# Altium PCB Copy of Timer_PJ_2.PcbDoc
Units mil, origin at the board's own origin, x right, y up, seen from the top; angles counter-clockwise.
Board outline 6000 x 4000 mil, 2 copper layers (Top Layer, Bottom Layer); 19 components, 12 nets, 42 pads, 0 vias.
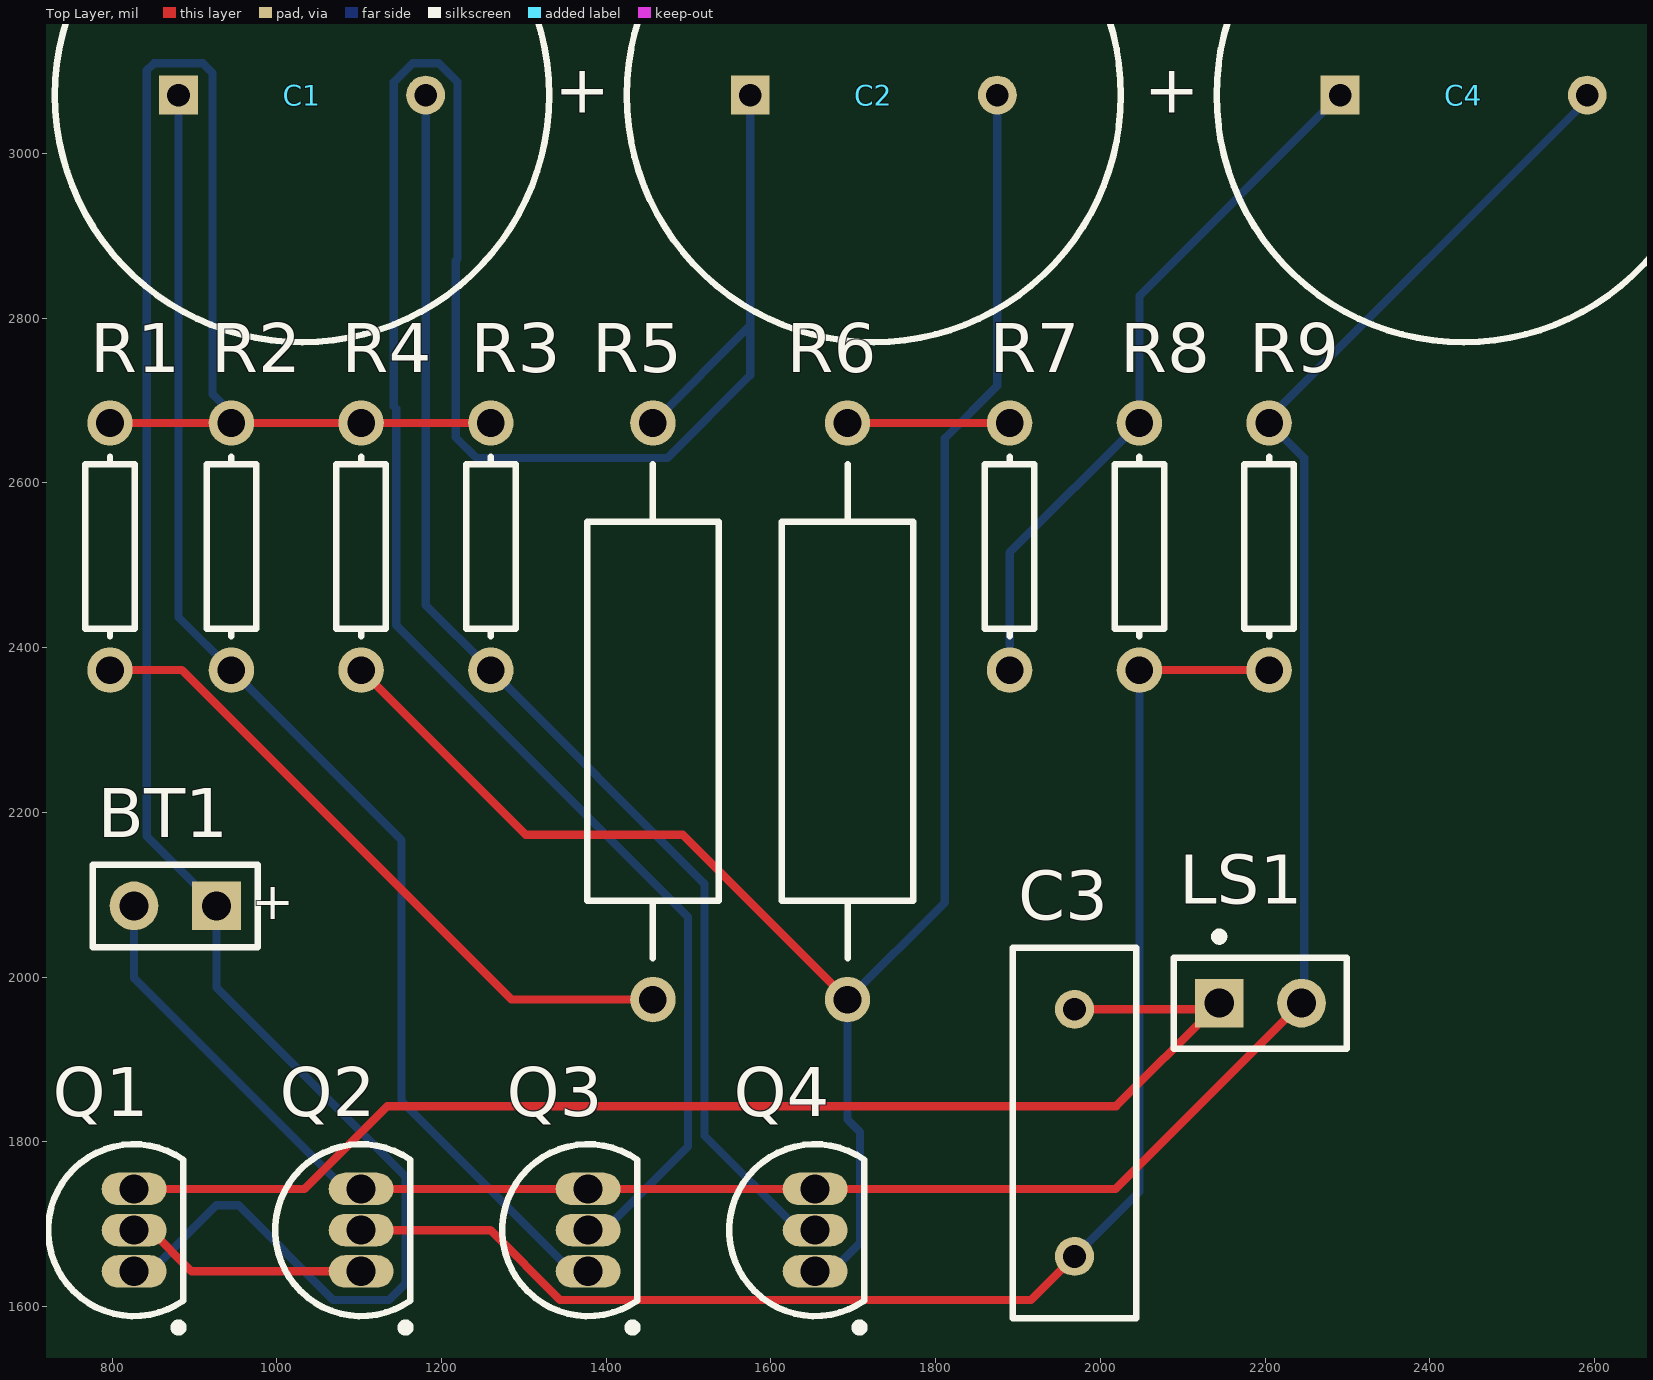
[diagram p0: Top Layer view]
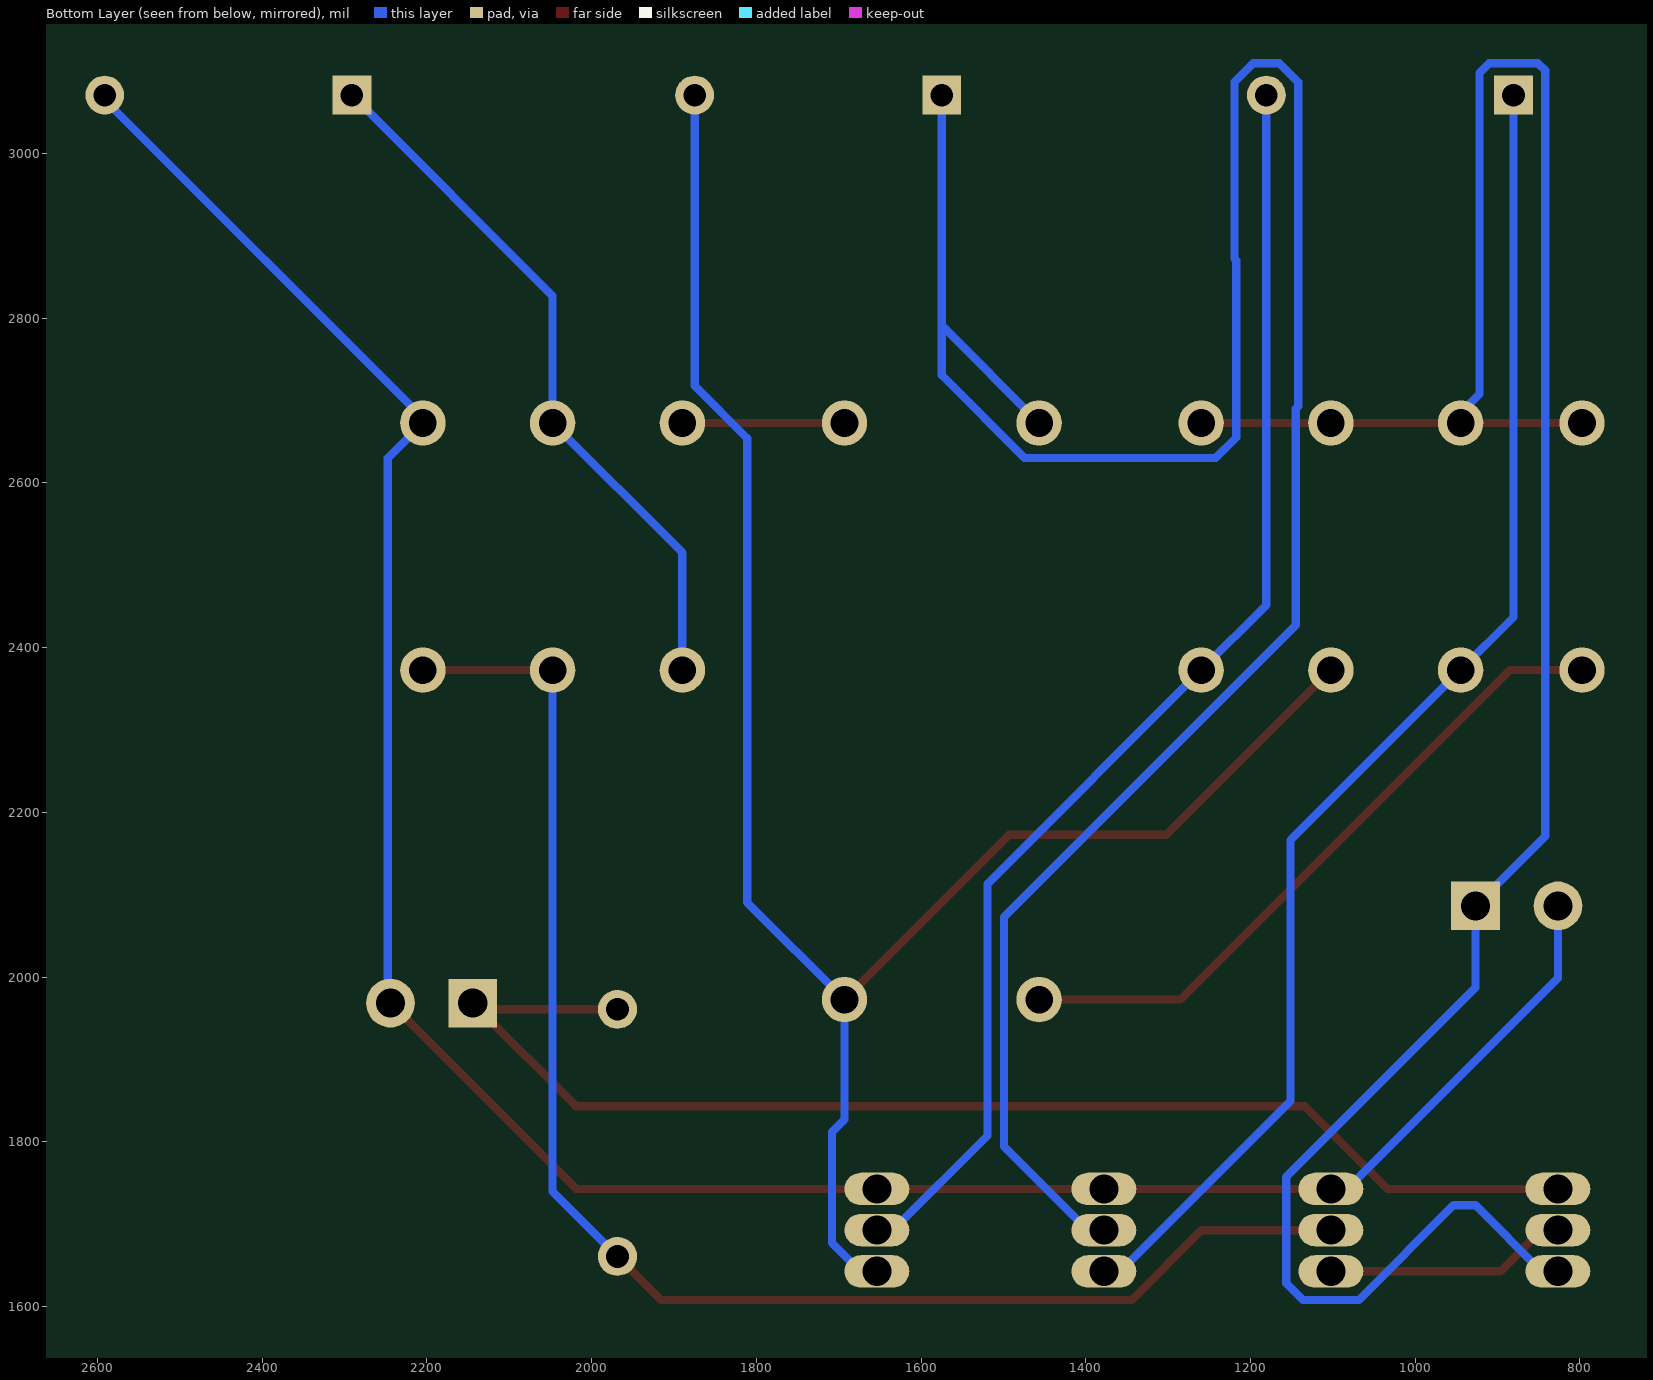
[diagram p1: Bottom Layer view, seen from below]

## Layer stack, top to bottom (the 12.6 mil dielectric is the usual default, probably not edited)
Top Solder: solder mask 0.4, Solder Resist, Dk 3.5
Top Layer: signal copper 1.4
Dielectric 1: dielectric 12.6, FR-4, Dk 4.8
Bottom Layer: signal copper 1.4
Bottom Solder: solder mask 0.4, Solder Resist, Dk 3.5

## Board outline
15.75,15.75 6015.75,15.75 6015.75,4015.75 15.75,4015.75

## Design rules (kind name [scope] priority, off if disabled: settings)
Clearance [All] p1: gap=10 ignorepadtopadclearanceinfootprint=FALSE except(0: Arc-Hole Track-Hole SMDPad-Hole THPad-Hole Via-Hole Fill-Hole Poly-Hole Region-Hole Text-Hole)
PolygonConnect [All] p1: connectstyle=Relief reliefconductorwidth=10 reliefentries=4 polygonreliefangle="90 Angle" airgapwidth=10
RoutingVias [All] p1: holewidth=28 width=50 viastyle="Through Hole" minholewidth=28 minwidth=50 maxholewidth=28 maxwidth=50
SolderMaskExpansion [All] p1: expansion=4 istentingtop=FALSE
Width [All] p1: maxlimit=10 minlimit=10 preferedwidth=10
30 further rules are at their usual default settings.

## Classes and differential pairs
component class Timer_PJ: BT1 C1 C3 C4 LS1 Q1 Q2 Q3 Q4 R1 R2 R3 R4 R5 R6 R7 R9

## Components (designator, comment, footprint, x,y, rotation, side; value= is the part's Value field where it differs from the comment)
BT1 "Battery" BAT-2 876.77,2086.61 r180 top
C1 "Cap Pol1" RB7.6-15 1030.75,3070.87 r180 top value=220uF
C2 "Cap Pol1" RB7.6-15 1724.8,3070.87 r180 top value=220uF
C3 "Cap" RAD-0.3 1968.5,1811.02 r90 top value=0.02uF
C4 "Cap Pol1" RB7.6-15 2440.94,3070.87 r180 top value=220uF
LS1 "Speaker" PIN2 2144.09,1968.5 r0 top
Q1 "NPN" TO-226-AA 826.77,1692.91 r0 top
Q2 "NPN" TO-226-AA 1102.36,1692.91 r0 top
Q3 "NPN" TO-226-AA 1377.95,1692.91 r0 top
Q4 "NPN" TO-226-AA 1653.54,1692.91 r0 top
R1 "Res1" AXIAL-0.3 797.56,2522.83 r270 top value=4.7K
R2 "Res1" AXIAL-0.3 944.88,2522.83 r270 top value=3.9K
R3 "Res1" AXIAL-0.3 1259.84,2522.83 r270 top value=10K
R4 "Res1" AXIAL-0.3 1102.36,2522.83 r270 top value=3.9K
R5 "Res Adj1" AXIAL-0.7 1456.69,2322.83 r90 top value=47K
R6 "Res Adj1" AXIAL-0.7 1692.91,2322.83 r90 top value=100K
R7 "Res1" AXIAL-0.3 1889.76,2522.83 r90 top value=10K
R8 "Res1" AXIAL-0.3 2047.24,2522.83 r90 top value=100K
R9 "Res1" AXIAL-0.3 2204.72,2522.83 r90 top value=47K

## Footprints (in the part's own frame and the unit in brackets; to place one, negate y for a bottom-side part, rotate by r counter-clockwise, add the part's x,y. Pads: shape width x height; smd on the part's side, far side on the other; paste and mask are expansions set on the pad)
AXIAL-0.3 [mm] "Axial Device, Thru-Hole; 2 Leads; 0.3 in Pin Spacing"
  round 1.4 hole 0.85: 1(-3.81,0) 2(3.81,0)
  silkscreen extent -2.77,-0.76 2.77,0.76
AXIAL-0.7 [mm] "Axial Device, Thru-Hole; 2 Leads; 0.7 in Pin Spacing"
  round 1.4 hole 0.85: 1(-8.89,0) 2(8.89,0)
  silkscreen extent -7.62,-2.03 7.62,2.03
BAT-2 [mm] "Battery; 2 Leads"
  rect 1.5x1.5 hole 0.9: 1(-1.27,0)
  round 1.5 hole 0.9: 2(1.27,0)
  silkscreen extent -2.54,-1.27 2.54,1.27
PIN2 [mm] "Photosensitive Diode; 2 Leads"
  rect 1.5x1.5 hole 0.9: 1(0,0)
  round 1.5 hole 0.9: 2(2.54,0)
  silkscreen extent -1.4,-1.4 3.94,2.17
RAD-0.3 [mm] "Radial Cap, Thru-Hole; 2 Leads; 0.3 in Pin Spacing"
  round 1.2 hole 0.7: 1(-3.81,0) 2(3.81,0)
  silkscreen extent -5.71,-1.91 5.71,1.91
RB7.6-15 [mm] "Polarized Capacitor (Radial); 2 Leads"
  rect 1.2x1.2 hole 0.7: 1(3.81,0)
  round 1.2 hole 0.7: 2(-3.81,0)
  silkscreen extent -7.62,-7.62 7.62,7.62
TO-226-AA [mm] "TO, Flat Index; 3 In-Line, Axial Leads; Body Dia. 4.8mm; Leads 0.55 x 0.51 mm (max)"
  oval 2x1 hole 0.9: 1(0,-1.27) 2(0,0) 3(0,1.27)
  silkscreen extent -2.65,-3.13 1.52,2.65, body extent -2.65,-2.66 1.52,2.66, height 5.33

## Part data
BT1: "Multicell Battery"
C1 C2 C4: "Polarized Capacitor (Radial)"
C3: "Capacitor"
LS1: "Loudspeaker"
Q1 Q2 Q3 Q4: "NPN Bipolar Transistor"
R1 R2 R3 R4 R7 R8 R9: "Resistor"
R5 R6: "Variable Resistor"

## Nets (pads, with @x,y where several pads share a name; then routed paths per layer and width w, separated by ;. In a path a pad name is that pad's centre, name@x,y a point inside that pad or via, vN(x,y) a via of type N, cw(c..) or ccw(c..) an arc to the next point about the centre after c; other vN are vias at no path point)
GND: BT1.2 C4.2 LS1.2 Q2.3 Q3.3 Q4.3 R9.2 | length 2985.8
  Top Layer w10: Q2.3 Q3.3 Q4.3 2018.5,1742.91 LS1.2
  Bottom Layer w10: BT1.2 826.77,1998.82 1082.68,1742.91 Q2.3 ; LS1.2 2247.28,1971.69 2247.28,2630.28 R9.2 2204.72,2678.74 2590.94,3064.96 C4.2
NetC1_1: C1.1 Q3.1 R2.2 | length 1645.4
  Bottom Layer w10: C1.1 880.75,2436.97 R2.2 1151.33,2166.38 1151.33,1849.85 1358.27,1642.91 Q3.1
NetC1_2: C1.2 Q4.2 R3.2 | length 1585.3
  Bottom Layer w10: C1.2 1180.75,2451.93 R3.2 1519.25,2113.43 1519.25,1807.52 1633.86,1692.91 Q4.2
NetC2_1: C2.1 Q3.2 R5.2 | length 3048.8
  Bottom Layer w10: Q3.2 1397.64,1692.91 1499.25,1794.53 1499.25,2073.24 1144.92,2427.57 1144.92,2690.46 1142.13,2693.26 1142.13,3086.86 1164.75,3109.49 1196.75,3109.49 1219.37,3086.86 1219.37,2872.08 1217.28,2869.99 1217.28,2655.21 1242.21,2630.28 1474.32,2630.28 1574.8,2730.76 1574.8,2790.94 ; R5.2 1574.8,2790.94 ; C2.1 1574.8,2790.94
NetC2_2: C2.2 Q4.1 R4.2 R6.1 | length 2299.8
  Top Layer w10: R4.2 1302.36,2172.83 1492.91,2172.83 R6.1
  Bottom Layer w10: Q4.1 1673.23,1642.91 1707.91,1677.6 1707.91,1812.09 1692.91,1827.09 R6.1 1811.02,2090.94 1811.02,2654.28 1874.8,2718.06 C2.2
NetC3_1: C3.1 Q2.2 R8.1 R9.1 | length 1825
  Top Layer w10: Q2.2 1259.22,1692.91 1343.9,1608.23 1915.71,1608.23 C3.1 ; R8.1 R9.1
  Bottom Layer w10: C3.1 2047.24,1739.76 R8.1
NetC3_2: C3.2 LS1.1 Q1.3 | length 1578.9
  Top Layer w10: Q1.3 1033.63,1742.91 1134.16,1843.45 2019.04,1843.45 LS1.1@2136.61,1961.02 ; C3.2 LS1.1@2136.61,1961.02 ; LS1.1 LS1.1@2136.61,1961.02
NetC4_1: C4.1 R7.1 R8.2 | length 864.2
  Bottom Layer w10: R7.1 1889.76,2515.35 R8.2 2047.24,2827.17 C4.1
NetQ1_2: Q1.2 Q2.1 | length 296.3
  Top Layer w10: Q1.2 846.46,1692.91 896.46,1642.91 Q2.1
NetR1_2: R1.2 R5.1 | length 824.8
  Top Layer w10: R1.2 884.69,2372.83 1284.69,1972.83 R5.1
NetR6_2: R6.2 R7.2 | length 196.9
  Top Layer w10: R6.2 R7.2
VCC: BT1.1 Q1.1 R1.1 R2.1 R3.1 R4.1 | length 3007
  Top Layer w10: R1.1 R2.1 R4.1 R3.1
  Bottom Layer w10: Q1.1 846.46,1642.91 926.77,1723.23 953.31,1723.23 1068.31,1608.23 1136.41,1608.23 1156.73,1628.55 1156.73,1757.28 926.77,1987.24 BT1.1 842.13,2171.26 842.13,3100.7 850.91,3109.49 910.58,3109.49 922.11,3097.96 922.11,2707.82 944.88,2685.04 R2.1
